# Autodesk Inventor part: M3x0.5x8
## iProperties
Company: 한국ATC센터
Created: 2009-02
Part Number: M3x0.5x8
Document SubType Name: Modeling
Designer: KYOUNG IL JANG
Density: 2.71 g/cm^3
Material: 알루미늄-6061
Mass: 23.7345 g
Surface Area: 33.7774 cm^2
Volume: 8.75813 cm^3
Vendor: CBT Solutions
Author: KYOUNG IL JANG
